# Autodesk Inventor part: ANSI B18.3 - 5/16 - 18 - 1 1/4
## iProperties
Comments: To add or edit properties for Autodesk Inventor files, use iProperties.
Created: 2005-06
Part Number: ANSI B18.3 - 5/16 - 18 - 1 1/4
Vendor: Autodesk Inc.
Document SubType Name: Modeling
Designer: John Blackburn
Material: Default
Description: Hexagon Socket Head Cap Screw
Standard: ANSI B18.3
Size Designation: 5/16 - 18 - 1 1/4
Alert: To add or edit properties for Autodesk Inventor files, use iProperties.
Control State: 0
Master: False
Checked Out: False
Shininess: 64.0
Length Units: 11272
Angle Units: 11279
Time Units: 11290
Mass Units: 11286
Length Display Precision: 3
Angle Display Precision: 2
Compacted: True
EGR: 3
Classification: un/spsc 31161501
Density: 0.0
Volumn: 0.0
Area: 0.0
PropertySet Name: Model Information
Author: John Blackburn
Revision Number: 8
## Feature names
1. Body [Revolution]
2. Slot [Extrusion]
3. Fillet1
4. Chamfer1
